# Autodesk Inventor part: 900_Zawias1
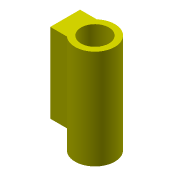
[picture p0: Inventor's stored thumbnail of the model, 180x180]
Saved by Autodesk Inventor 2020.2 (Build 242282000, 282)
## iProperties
Created: 2006-01
Part Number: 900_Zawias1
Document SubType Name: Modeling
Designer: F.Stasiak
Density: 1 g/cm^3
Material: Ogólny
Appearance: Żółty
Manager: www.cadconsulting.pl
Company: Fabian Stasiak CAD Consulting
Author: F.Stasiak
Subject: Zbiór ćwiczeń. Autodesk Inventor 2020. Kurs podstawowy
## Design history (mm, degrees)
sketch "Szkic1"
  geometry: C1 r 10 at (0, 0); 1 further point
  constraints: 1 centre point, 1 coincident
  dimensions: "d0" = 20 diameter of C1
extrude "Wyciągnięcie proste1" new body sketch "Szkic1" distance "d1" = 50; taper "d2" = 0 deg
feature "Skorupa1" dims "d4" = 3
sketch "Szkic2"
  geometry: L1 (-6.614, 7.5)-(-15, 7.5); L2 (-15, 7.5)-(-15, -7.5); L3 (-15, -7.5)-(-6.614, -7.5); L4 (-15, 0)-(0, 0); C1 r 7 at (0, 0) reference; A1 r 10 centre (0, 0) between (-6.614, 7.5) and (-6.614, -7.5) reference
  constraints: 8 end point, 2 parallel, 2 point on circle, 1 horizontal, 1 midpoint, 1 perpendicular
  dimensions: "d5" = 15 distance from line of C1.centre L2; "d6" = 15 distance of L1.end L2.end
extrude "Wyciągnięcie proste2" join sketch "Szkic2" distance "d7" = 40; taper "d8" = 0 deg
node "Bryła1"
node "Korpusy bryłowe"
node "Korpusy powierzchniowe"
